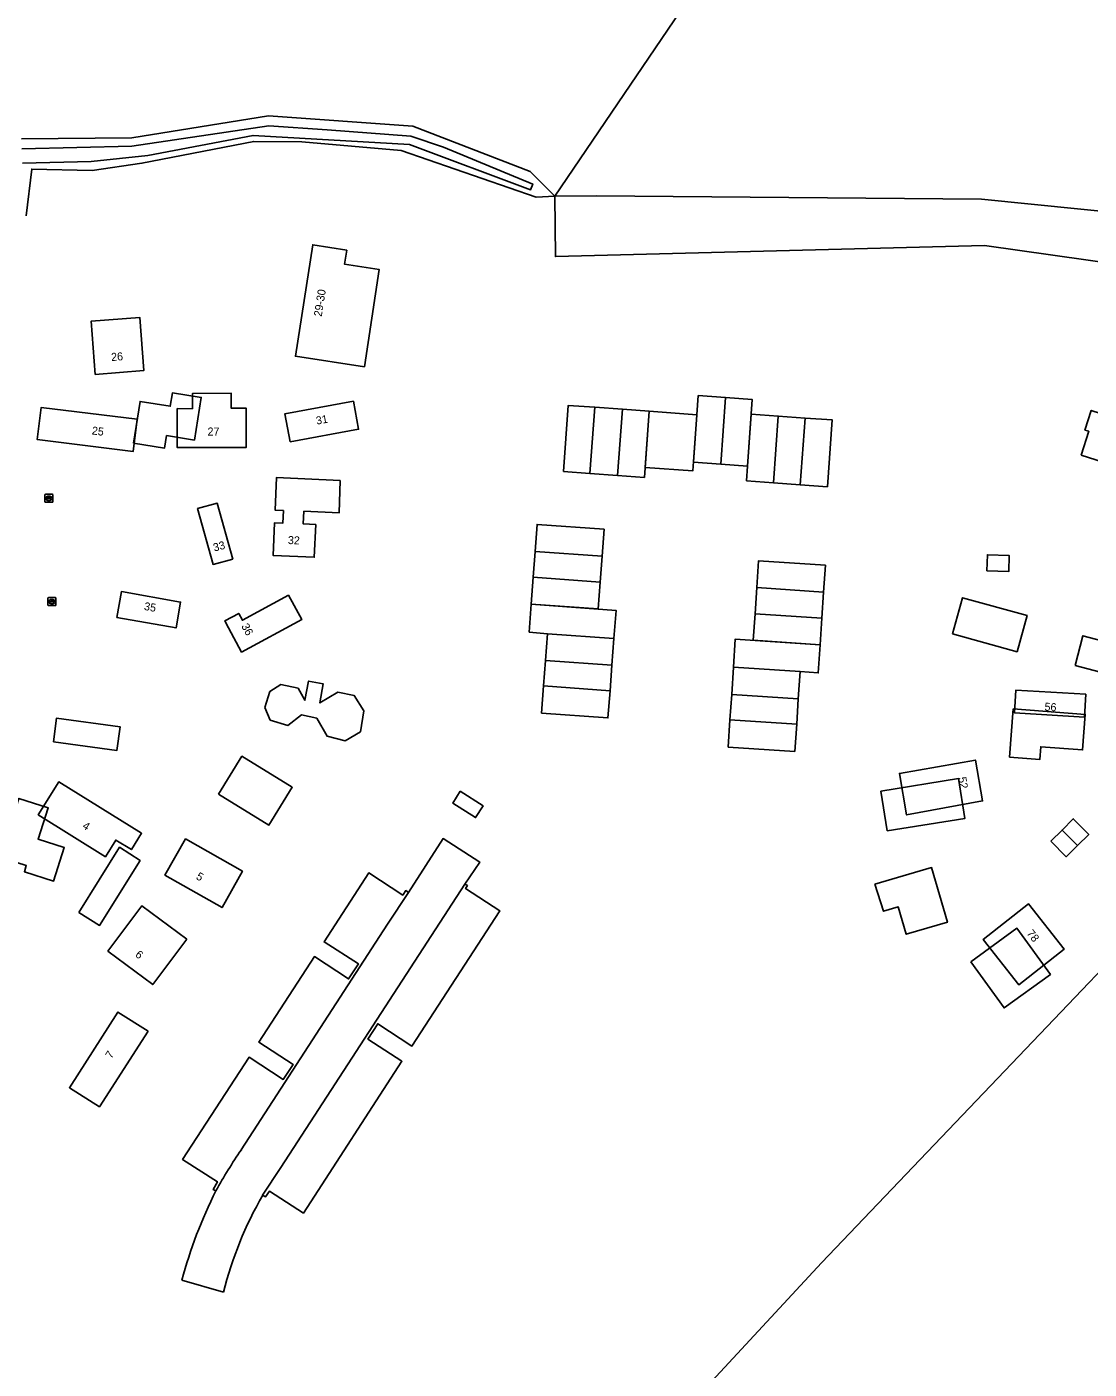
# Model space of a CAD drawing. Extents: x 159451 to 160664, y 388402 to 389723.
# Drawn here: x 160093.8 to 160226.5, y 389378.7 to 389546.4 of the extents above; entities that cross this region are included whole.
import ezdxf

# ---------------------------------------------------------------- set-up
doc = ezdxf.new("R2010")
doc.units = 0
for name, color, linetype in [('IMGEO_Groenvoorziening', 7, 'Continuous'), ('IMGEO_Lage_trafo', 7, 'Continuous'), ('IMGEO_Oever', 7, 'Continuous'), ('IMGEO_Pand', 7, 'Continuous'), ('IMGEO_Pand_nummerreeks', 7, 'Continuous'), ('IMGEO_Pand_vergunning_verleend', 7, 'Continuous'), ('IMGEO_Parkeervlak_halfverhard', 7, 'Continuous'), ('IMGEO_Rijbaan_lokaal_gesloten', 7, 'Continuous'), ('IMGEO_Rioolput', 7, 'Continuous'), ('IMGEO_Voetpad_open', 7, 'Continuous'), ('IMGEO_Waterloop', 7, 'Continuous')]:
    doc.layers.add(name, color=color, linetype=linetype)

msp = doc.modelspace()

# ---------------------------------------------------------------- linework, layer by layer
at = {"layer": 'IMGEO_Groenvoorziening'}
for points in [[(160093.1, 389532.4), (160106.88, 389532.52), (160123.96, 389535.27), (160141.97, 389533.98), (160156.63, 389528.31), (160159.71, 389525.23), (160191.12, 389571.55)], [(160237.78, 389558.66), (160226.18, 389562.3), (160215.01, 389566.48), (160209.97, 389567.79), (160204.81, 389568.79), (160199.48, 389569.98), (160191.12, 389571.55), (160159.71, 389525.23), (160164.89, 389525.24), (160213.01, 389524.85), (160288.33, 389517.26)], [(160359.11, 389498.45), (160213.4, 389519.05), (160159.78, 389517.67), (160159.71, 389525.23), (160157.4, 389525.1), (160140.5, 389530.91), (160128.13, 389532), (160122.1, 389532.06), (160108.14, 389529.34), (160101.92, 389528.44), (160094.37, 389528.6), (160093.68, 389522.77)], [(160160.93, 389357.29), (160193.04, 389391.96), (160260.8, 389462.93)], [(160260.8, 389462.93), (160193.04, 389391.96), (160160.93, 389357.29)], [(160117.38, 389400.94), (160117.03, 389401.12), (160117.57, 389402.08), (160113.22, 389404.87), (160121.53, 389417.63), (160125.79, 389414.87), (160127.01, 389416.74), (160122.74, 389419.51), (160129.68, 389430.2), (160133.95, 389427.42), (160135.17, 389429.29), (160130.89, 389432.05), (160136.47, 389440.66), (160140.71, 389437.9), (160141.1, 389438.45), (160141.43, 389438.23), (160145.75, 389444.96), (160150.34, 389442.02)], [(160150.34, 389442.02), (160148.48, 389439.26), (160148.79, 389439.07), (160148.56, 389438.7), (160152.84, 389435.93), (160141.86, 389419.02), (160137.6, 389421.81), (160136.36, 389419.9), (160140.62, 389417.13), (160128.3, 389398.15), (160124.05, 389400.89), (160123.57, 389400.17), (160123.21, 389400.4)], [(160118.33, 389388.29), (160113.12, 389389.79)]]:
    msp.add_lwpolyline(points, dxfattribs=at)
for points in [[(160127.3, 389505.22), (160129.47, 389519.14), (160133.73, 389518.47), (160133.46, 389516.72), (160137.76, 389516.06), (160135.92, 389503.91)], [(160108.36, 389503.42), (160102.3, 389502.95), (160101.8, 389509.61), (160107.87, 389510.07)], [(160121.17, 389493.82), (160112.55, 389493.81), (160112.55, 389498.67), (160114.43, 389498.66), (160114.43, 389500.55), (160119.29, 389500.59), (160119.29, 389498.71), (160121.17, 389498.71)], [(160107.02, 389493.3), (160095.05, 389494.8), (160095.55, 389498.83), (160107.52, 389497.34)], [(160126.65, 389494.53), (160126, 389498.04), (160134.56, 389499.6), (160135.2, 389496.09)], [(160132.76, 389485.65), (160128.36, 389485.84), (160128.29, 389484.26), (160129.84, 389484.19), (160129.66, 389480.11), (160124.52, 389480.33), (160124.7, 389484.42), (160125.74, 389484.37), (160125.81, 389485.94), (160124.77, 389485.99), (160124.95, 389490.08), (160132.88, 389489.68)], [(160119.49, 389479.88), (160117.02, 389479.2), (160115.08, 389486.18), (160117.54, 389486.85)], [(160112.39, 389471.28), (160105.01, 389472.59), (160105.57, 389475.82), (160112.97, 389474.51)], [(160128.12, 389472.33), (160120.58, 389468.25), (160118.93, 389471.27), (160118.48, 389472.14), (160120.22, 389473.09), (160120.68, 389472.23), (160126.43, 389475.36)], [(160226.06, 389462.98), (160225.88, 389460.14), (160217.15, 389460.66), (160217.33, 389463.5)], [(160213.16, 389449.65), (160203.67, 389447.9), (160202.76, 389453.09), (160212.26, 389454.75)], [(160108.09, 389445.62), (160106.81, 389443.57), (160104.87, 389444.76), (160103.57, 389442.69), (160095.18, 389447.92), (160097.75, 389452.04)], [(160147.91, 389450.86), (160150.76, 389449.03), (160149.82, 389447.57), (160146.97, 389449.39)], [(160120.69, 389440.86), (160118.14, 389436.32), (160111.01, 389440.4), (160113.58, 389444.9)], [(160113.73, 389432.37), (160109.49, 389426.71), (160103.89, 389430.89), (160108.13, 389436.56)], [(160217.67, 389426.68), (160213.24, 389432.36), (160218.9, 389436.78), (160223.33, 389431.12)], [(160108.93, 389420.88), (160102.83, 389411.44), (160099.07, 389413.81), (160105.14, 389423.28)]]:
    msp.add_lwpolyline(points, close=True, dxfattribs=at)
for centre, radius, start, end in [((160170.72, 389374.2), 59.67, 153.3759, 164.8558), ((160164.95, 389376.5), 48.09, 150.2054, 165.8137)]:
    msp.add_arc(centre, radius, start, end, dxfattribs=at)
at = {"layer": 'IMGEO_Lage_trafo'}
msp.add_lwpolyline([(160147.91, 389450.86), (160146.97, 389449.39), (160149.82, 389447.57), (160150.76, 389449.03)], close=True, dxfattribs=at)
at = {"layer": 'IMGEO_Oever'}
for points in [[(160093.68, 389522.77), (160094.37, 389528.6), (160101.92, 389528.44), (160108.14, 389529.34), (160122.1, 389532.06), (160128.13, 389532), (160140.5, 389530.91), (160157.4, 389525.1), (160159.71, 389525.23), (160156.63, 389528.31), (160141.97, 389533.98), (160123.96, 389535.27), (160106.88, 389532.52), (160093.1, 389532.4)], [(160093.15, 389531.13), (160106.86, 389531.48), (160124, 389533.99), (160131.26, 389533.49), (160141.73, 389532.72), (160145.82, 389531.36), (160156.96, 389526.73), (160156.68, 389526.02), (160141.58, 389531.66), (160122.02, 389532.8), (160108.87, 389530.29), (160101.81, 389529.55), (160093.23, 389529.36)]]:
    msp.add_lwpolyline(points, dxfattribs=at)
at = {"layer": 'IMGEO_Pand'}
for points in [[(160137.76, 389516.06), (160133.46, 389516.72), (160133.73, 389518.47), (160129.47, 389519.14), (160127.3, 389505.22), (160135.92, 389503.91)], [(160107.87, 389510.07), (160101.8, 389509.61), (160102.3, 389502.95), (160108.36, 389503.42)], [(160121.17, 389498.71), (160119.29, 389498.71), (160119.29, 389500.59), (160114.43, 389500.55), (160114.43, 389498.66), (160112.55, 389498.67), (160112.55, 389493.81), (160121.17, 389493.82)], [(160107.52, 389497.34), (160095.55, 389498.83), (160095.05, 389494.8), (160107.02, 389493.3)], [(160126.65, 389494.53), (160135.2, 389496.09), (160134.56, 389499.6), (160126, 389498.04)], [(160128.36, 389485.84), (160132.76, 389485.65), (160132.88, 389489.68), (160124.95, 389490.08), (160124.77, 389485.99), (160125.81, 389485.94), (160125.74, 389484.37), (160124.7, 389484.42), (160124.52, 389480.33), (160129.66, 389480.11), (160129.84, 389484.19), (160128.29, 389484.26)], [(160119.49, 389479.88), (160117.54, 389486.85), (160115.08, 389486.18), (160117.02, 389479.2)], [(160112.97, 389474.51), (160105.57, 389475.82), (160105.01, 389472.59), (160112.39, 389471.28)], [(160126.43, 389475.36), (160120.68, 389472.23), (160120.22, 389473.09), (160118.48, 389472.14), (160118.93, 389471.27), (160120.58, 389468.25), (160128.12, 389472.33)], [(160226.06, 389462.98), (160217.33, 389463.5), (160217.15, 389460.66), (160225.88, 389460.14)], [(160202.76, 389453.09), (160203.67, 389447.9), (160213.16, 389449.65), (160212.26, 389454.75)], [(160095.18, 389447.92), (160103.57, 389442.69), (160104.87, 389444.76), (160106.81, 389443.57), (160108.09, 389445.62), (160097.75, 389452.04)], [(160113.58, 389444.9), (160111.01, 389440.4), (160118.14, 389436.32), (160120.69, 389440.86)], [(160113.73, 389432.37), (160108.13, 389436.56), (160103.89, 389430.89), (160109.49, 389426.71)], [(160213.24, 389432.36), (160217.67, 389426.68), (160223.33, 389431.12), (160218.9, 389436.78)], [(160108.93, 389420.88), (160105.14, 389423.28), (160099.07, 389413.81), (160102.83, 389411.44)]]:
    msp.add_lwpolyline(points, close=True, dxfattribs=at)
at = {"layer": 'IMGEO_Pand_vergunning_verleend'}
for points in [[(160107.07, 389494.35), (160107.91, 389499.58), (160111.68, 389498.97), (160111.96, 389500.66), (160115.54, 389500.08), (160114.7, 389494.74), (160111.21, 389495.31), (160110.95, 389493.72)], [(160177.03, 389491.97), (160177.46, 389497.91), (160177.63, 389500.3), (160181.04, 389500.05), (160180.44, 389491.72)], [(160180.44, 389491.72), (160181.04, 389500.05), (160184.39, 389499.81), (160183.79, 389491.48)], [(160160.8, 389490.8), (160161.39, 389499.08), (160164.71, 389498.84), (160164.11, 389490.56)], [(160164.11, 389490.56), (160164.71, 389498.84), (160168.16, 389498.59), (160167.56, 389490.31)], [(160167.56, 389490.31), (160168.16, 389498.59), (160171.49, 389498.34), (160170.9, 389490.07)], [(160170.99, 389491.33), (160171.49, 389498.34), (160177.46, 389497.91), (160176.95, 389490.89)], [(160225.46, 389492.87), (160226.41, 389495.84), (160225.95, 389495.99), (160226.73, 389498.44), (160233.07, 389496.41), (160232.26, 389493.88), (160231.88, 389494), (160230.95, 389491.1)], [(160183.66, 389489.65), (160183.79, 389491.48), (160184.26, 389497.99), (160187.63, 389497.75), (160187.02, 389489.4)], [(160187.02, 389489.4), (160187.63, 389497.75), (160190.98, 389497.5), (160190.38, 389489.16)], [(160190.38, 389489.16), (160190.98, 389497.5), (160194.38, 389497.26), (160193.78, 389488.92)], [(160157.25, 389480.84), (160157.5, 389484.2), (160165.86, 389483.6), (160165.62, 389480.24)], [(160157.02, 389477.6), (160157.25, 389480.84), (160165.62, 389480.24), (160165.38, 389477)], [(160213.69, 389478.42), (160213.76, 389480.41), (160216.49, 389480.32), (160216.42, 389478.32)], [(160184.94, 389476.31), (160185.16, 389479.64), (160193.52, 389479.1), (160193.3, 389475.76)], [(160156.78, 389474.25), (160157.02, 389477.6), (160165.38, 389477), (160165.14, 389473.65)], [(160184.73, 389473.05), (160184.94, 389476.31), (160193.3, 389475.76), (160193.08, 389472.5)], [(160209.38, 389470.53), (160210.64, 389475.05), (160218.72, 389472.81), (160217.46, 389468.29)], [(160156.52, 389470.73), (160156.78, 389474.25), (160167.36, 389473.46), (160167.09, 389469.93), (160158.81, 389470.55)], [(160184.51, 389469.73), (160184.73, 389473.05), (160193.08, 389472.5), (160192.86, 389469.18)], [(160158.56, 389467.22), (160158.81, 389470.55), (160167.09, 389469.93), (160166.84, 389466.6)], [(160182.03, 389466.35), (160182.26, 389469.88), (160192.86, 389469.18), (160192.63, 389465.66), (160190.36, 389465.81)], [(160224.72, 389466.58), (160225.7, 389470.29), (160238.18, 389466.99), (160237.2, 389463.29)], [(160158.32, 389464.04), (160158.56, 389467.22), (160166.84, 389466.6), (160166.61, 389463.42)], [(160181.81, 389462.95), (160182.03, 389466.35), (160190.36, 389465.81), (160190.13, 389462.4)], [(160123.48, 389461.35), (160124.1, 389463.32), (160125.48, 389464.19), (160127.64, 389463.76), (160128.49, 389462.24), (160128.96, 389464.62), (160130.77, 389464.3), (160130.36, 389461.9), (160132.6, 389463.26), (160134.66, 389462.81), (160135.84, 389460.9), (160135.44, 389458.31), (160133.54, 389457.17), (160131.27, 389457.73), (160129.98, 389460.01), (160128.06, 389460.43), (160126.37, 389459.09), (160124.17, 389459.75)], [(160158.07, 389460.64), (160158.32, 389464.04), (160166.61, 389463.42), (160166.35, 389460.02)], [(160181.6, 389459.79), (160181.81, 389462.95), (160190.13, 389462.4), (160189.93, 389459.25)], [(160097.08, 389457.05), (160097.48, 389460.01), (160105.41, 389458.92), (160105, 389455.96)], [(160181.38, 389456.39), (160181.6, 389459.79), (160189.93, 389459.25), (160189.7, 389455.84)], [(160216.53, 389455.13), (160216.99, 389461.15), (160225.98, 389460.46), (160225.64, 389456.03), (160220.43, 389456.43), (160220.31, 389454.84)], [(160117.69, 389450.51), (160120.63, 389455.24), (160126.92, 389451.37), (160124, 389446.63)], [(160200.44, 389450.89), (160210.16, 389452.44), (160210.95, 389447.48), (160201.24, 389445.93)], [(160090.42, 389442.62), (160092.77, 389449.97), (160096.42, 389448.81), (160095.16, 389444.87), (160098.43, 389443.83), (160097.09, 389439.64), (160093.45, 389440.81), (160093.69, 389441.57)], [(160223.08, 389446.02), (160224.49, 389447.42), (160226.41, 389445.48), (160225, 389444.08)], [(160221.67, 389444.62), (160223.08, 389446.02), (160225, 389444.08), (160223.59, 389442.68)], [(160100.26, 389435.72), (160105.34, 389443.87), (160107.9, 389442.21), (160102.84, 389434.11)], [(160199.68, 389439.25), (160206.78, 389441.32), (160208.77, 389434.49), (160203.62, 389432.99), (160202.62, 389436.41), (160200.76, 389435.87)], [(160211.68, 389429.57), (160217.45, 389433.75), (160221.62, 389427.97), (160215.85, 389423.8)]]:
    msp.add_lwpolyline(points, close=True, dxfattribs=at)
at = {"layer": 'IMGEO_Parkeervlak_halfverhard'}
for points in [[(160141.43, 389438.23), (160141.1, 389438.45), (160140.71, 389437.9), (160136.47, 389440.66), (160130.89, 389432.05), (160135.17, 389429.29), (160133.95, 389427.42), (160129.68, 389430.2), (160122.74, 389419.51), (160127.01, 389416.74), (160125.79, 389414.87), (160121.53, 389417.63), (160113.22, 389404.87), (160117.57, 389402.08), (160117.03, 389401.12), (160117.38, 389400.94)], [(160120.55, 389406.08), (160138.83, 389434.26), (160141.43, 389438.23)]]:
    msp.add_lwpolyline(points, dxfattribs=at)
msp.add_lwpolyline([(160148.48, 389439.26), (160125.49, 389403.86), (160123.21, 389400.4), (160123.57, 389400.17), (160124.05, 389400.89), (160128.3, 389398.15), (160140.62, 389417.13), (160136.36, 389419.9), (160137.6, 389421.81), (160141.86, 389419.02), (160152.84, 389435.93), (160148.56, 389438.7), (160148.79, 389439.07)], close=True, dxfattribs=at)
msp.add_arc((160168.1, 389373.19), 57.81, 145.3299, 151.3171, dxfattribs=at)
at = {"layer": 'IMGEO_Rijbaan_lokaal_gesloten'}
for points in [[(160123.21, 389400.4), (160125.49, 389403.86), (160148.48, 389439.26), (160150.34, 389442.02), (160145.75, 389444.96), (160141.43, 389438.23), (160138.83, 389434.26), (160120.55, 389406.08)], [(160113.12, 389389.79), (160118.33, 389388.29)]]:
    msp.add_lwpolyline(points, dxfattribs=at)
for centre, radius, start, end in [((160168.1, 389373.19), 57.81, 145.3299, 151.3171), ((160170.72, 389374.2), 59.67, 153.3759, 164.8558), ((160164.95, 389376.5), 48.09, 150.2054, 165.8137)]:
    msp.add_arc(centre, radius, start, end, dxfattribs=at)
at = {"layer": 'IMGEO_Rioolput'}
for p, q in [((160096.01, 389487.05), (160096.01, 389487.9)), ((160096.08, 389487.97), (160096.93, 389487.97)), ((160096.93, 389486.97), (160096.08, 389486.97)), ((160096.27, 389487.47), (160096.27, 389487.48)), ((160096.31, 389487.52), (160096.71, 389487.52)), ((160096.7, 389487.43), (160096.31, 389487.43)), ((160096.52, 389487.19), (160096.49, 389487.19)), ((160096.5, 389487.75), (160096.52, 389487.75)), ((160096.75, 389487.48), (160096.75, 389487.47)), ((160097.01, 389487.9), (160097.01, 389487.05)), ((160096.39, 389474.13), (160096.39, 389474.99)), ((160096.46, 389475.06), (160097.32, 389475.06)), ((160096.88, 389474.84), (160096.9, 389474.84)), ((160097.39, 389474.99), (160097.39, 389474.13)), ((160097.32, 389474.06), (160096.46, 389474.06)), ((160096.65, 389474.55), (160096.65, 389474.57)), ((160096.69, 389474.6), (160097.09, 389474.6)), ((160097.09, 389474.52), (160096.69, 389474.52)), ((160096.9, 389474.28), (160096.87, 389474.28)), ((160097.13, 389474.57), (160097.13, 389474.55))]:
    msp.add_line(p, q, dxfattribs=at)
for points in [[(160096.01, 389487.05), (160096.01, 389487.9)], [(160096.08, 389487.97), (160096.93, 389487.97)], [(160096.93, 389486.97), (160096.08, 389486.97)], [(160097.01, 389487.9), (160097.01, 389487.05)], [(160096.39, 389474.13), (160096.39, 389474.99)], [(160096.46, 389475.06), (160097.32, 389475.06)], [(160097.39, 389474.99), (160097.39, 389474.13)], [(160097.32, 389474.06), (160096.46, 389474.06)]]:
    msp.add_lwpolyline(points, dxfattribs=at)
for centre, radius, start, end in [((160096.08, 389487.9), 0.0765, 91.552, 178.448), ((160096.08, 389487.9), 0.0765, 91.552, 178.448), ((160096.08, 389487.05), 0.0765, 181.552, 268.448), ((160096.08, 389487.05), 0.0765, 181.552, 268.448), ((160096.31, 389487.48), 0.0403, 85.8775, 175.7526), ((160096.3, 389487.47), 0.0366, 178.938, 274.7102), ((160096.71, 389487.47), 0.043, 264.8664, 352.4533), ((160096.71, 389487.48), 0.0386, 1.7309, 96.639), ((160096.93, 389487.9), 0.0765, 1.552, 88.448), ((160096.93, 389487.9), 0.0765, 1.552, 88.448), ((160096.93, 389487.05), 0.0765, 271.552, 358.448), ((160096.93, 389487.05), 0.0765, 271.552, 358.448), ((160096.47, 389474.98), 0.0765, 91.552, 178.448), ((160096.47, 389474.98), 0.0765, 91.552, 178.448), ((160097.31, 389474.98), 0.0765, 1.552, 88.448), ((160097.31, 389474.98), 0.0765, 1.552, 88.448), ((160096.47, 389474.13), 0.0765, 181.552, 268.448), ((160096.47, 389474.13), 0.0765, 181.552, 268.448), ((160096.69, 389474.56), 0.0403, 85.8775, 175.7526), ((160096.68, 389474.55), 0.0366, 178.938, 274.7102), ((160097.09, 389474.56), 0.0386, 1.7309, 96.639), ((160097.09, 389474.56), 0.043, 264.8664, 352.4533), ((160097.31, 389474.13), 0.0765, 271.552, 358.448), ((160097.31, 389474.13), 0.0765, 271.552, 358.448)]:
    msp.add_arc(centre, radius, start, end, dxfattribs=at)
for centre, major_axis, ratio, start_param, end_param in [((160096.49, 389487.47), (-0.387, 0.002), 0.722429, 4.712389, 7.853982), ((160096.52, 389487.47), (-0.39, 0.002), 0.717154, 1.570796, 4.712389), ((160096.88, 389474.56), (-0.387, 0.002), 0.722429, 4.712389, 7.853982), ((160096.9, 389474.56), (-0.39, 0.002), 0.717154, 1.570796, 4.712389)]:
    msp.add_ellipse(centre, major_axis=major_axis, ratio=ratio, start_param=start_param, end_param=end_param, dxfattribs=at)
at = {"layer": 'IMGEO_Voetpad_open'}
msp.add_lwpolyline([(160288.33, 389517.26), (160213.01, 389524.85), (160164.89, 389525.24), (160159.71, 389525.23), (160159.78, 389517.67), (160213.4, 389519.05), (160359.11, 389498.45)], dxfattribs=at)
at = {"layer": 'IMGEO_Waterloop'}
msp.add_lwpolyline([(160093.23, 389529.36), (160101.81, 389529.55), (160108.87, 389530.29), (160122.02, 389532.8), (160141.58, 389531.66), (160156.68, 389526.02), (160156.96, 389526.73), (160145.82, 389531.36), (160141.73, 389532.72), (160131.26, 389533.49), (160124, 389533.99), (160106.86, 389531.48), (160093.15, 389531.13)], dxfattribs=at)

# ---------------------------------------------------------------- texts
at = {"layer": 'IMGEO_Pand_nummerreeks'}
for s, rotation, p in [('29-30', 81.1251, (160130.59, 389510.12)), ('26', 4.4576, (160104.32, 389504.61)), ('31', 10.3935, (160129.97, 389496.66)), ('25', 352.8609, (160101.83, 389495.46)), ('27', 0.0974, (160116.33, 389495.31)), ('33', 15.2922, (160117.18, 389480.8)), ('32', 357.4733, (160126.35, 389481.76)), ('35', 349.9331, (160108.34, 389473.53)), ('36', 298.5102, (160120.51, 389471.51)), ('56', 356.631, (160220.87, 389460.94)), ('52', 279.9406, (160210.11, 389452.57)), ('4', 328.0232, (160100.61, 389446.3)), ('5', 330.252, (160114.81, 389439.95)), ('78', 308.0556, (160218.61, 389433.09)), ('6', 323.2505, (160107.21, 389430.28)), ('7', 57.3473, (160104.33, 389417.38))]:
    msp.add_text(s, height=1, rotation=rotation, dxfattribs=at).set_placement(p)

doc.saveas('drawing.dxf')
